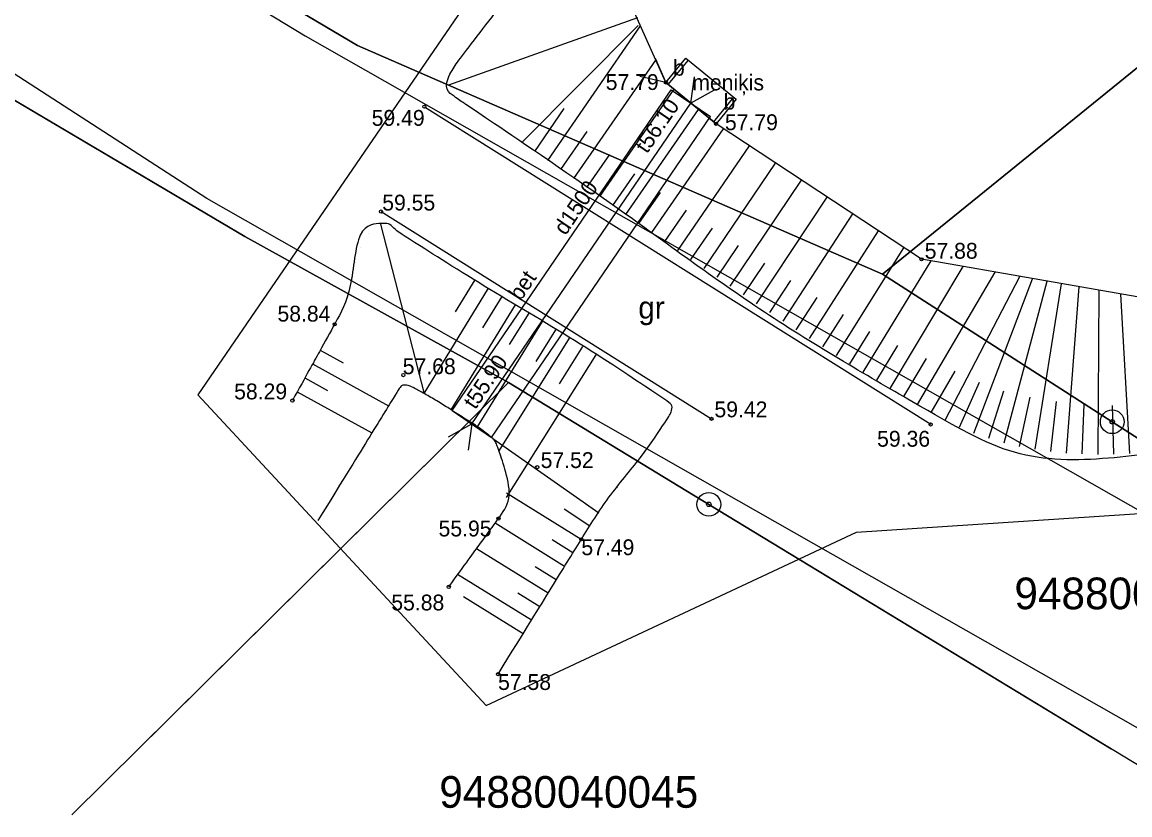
# Model space of a CAD drawing. Extents: x 616607 to 617499, y 408385 to 409695.
# Drawn here: x 616660.87 to 616695.86, y 408454.43 to 408479.45 of the extents above; entities that cross this region are included whole.
import ezdxf

# ---------------------------------------------------------------- set-up
doc = ezdxf.new("R2010")
doc.units = 0
for name, color, linetype in [('BUVE_BDET_####_####_#', 7, 'Continuous'), ('BUVE_BDET_####_TKST_#', 7, 'Continuous'), ('BUVE_INZE_VEKT_####_#', 7, 'Continuous'), ('CELI_CSEG_####_TKST_#', 7, 'Continuous'), ('CELI_TAKA_####_####_#', 7, 'Continuous'), ('HIDG_GRAV_####_####_#', 7, 'Continuous'), ('HIDG_PLIN_####_####_#', 7, 'Continuous'), ('HIDT_CAUR_####_####_#', 7, 'Continuous'), ('HIDT_CAUR_####_TKST_#', 7, 'Continuous'), ('HIDT_CAUR_KONT_####_#', 7, 'Continuous'), ('HIDT_ELEM_####_####_#', 7, 'Continuous'), ('RAMI_UZMR_####_####_#', 7, 'Continuous'), ('RELJ_AATZ_####_TKST_#', 7, 'Continuous'), ('RELJ_ELEM_####_####_#', 7, 'Continuous'), ('RELJ_NOGA_####_####_#', 7, 'Continuous'), ('ROBZ_IERR_####_####_#', 7, 'Continuous'), ('ROBZ_PROJ_####_####_#', 7, 'Continuous'), ('ROBZ_PROJ_####_TKST_#', 7, 'Continuous'), ('ROBZ_ROBP_####_####_#', 7, 'Continuous'), ('ROBZ_UZMR_####_####_#', 7, 'Continuous'), ('ROBZ_UZMR_####_TKST_#', 7, 'Continuous')]:
    doc.layers.add(name, color=color, linetype=linetype)

# ---------------------------------------------------------------- blocks, each defined once
blk = doc.blocks.new('PKT')
at = {"layer": 'RELJ_ELEM_####_####_#'}
blk.add_circle((0, 0), 0.05, dxfattribs=at)
blk = doc.blocks.new('CAURT')
at = {"layer": 'HIDT_ELEM_####_####_#'}
blk.add_lwpolyline([(0.75, -0.374), (0, 0), (0.75, 0.376)], dxfattribs=at)
blk = doc.blocks.new('KUPICA')
at = {"layer": 'ROBZ_ROBP_####_####_#'}
for radius in [0.375, 0.0702, 0.0702]:
    blk.add_circle((0, 0), radius, dxfattribs=at)

msp = doc.modelspace()

# ---------------------------------------------------------------- linework, layer by layer
at = {"layer": 'BUVE_BDET_####_####_#'}
for p, q in [((616681.206, 408477.551), (616681.842, 408478.323)), ((616681.283, 408477.488), (616681.919, 408478.26)), ((616681.842, 408478.323), (616683.426, 408477.019)), ((616683.349, 408477.082), (616682.714, 408476.31)), ((616683.426, 408477.019), (616682.791, 408476.247))]:
    msp.add_line(p, q, dxfattribs=at)
msp.add_lwpolyline([(616681.206, 408477.551), (616682.791, 408476.247)], dxfattribs=at)
at = {"layer": 'BUVE_INZE_VEKT_####_#'}
for points in [[(616654.058, 408488.574), (616669.817, 408479.019), (616700.989, 408461.293)], [(616697.261, 408456.511), (616666.703, 408473.888), (616651.742, 408483.567)]]:
    msp.add_lwpolyline(points, dxfattribs=at)
at = {"layer": 'CELI_TAKA_####_####_#'}
for points in [[(616673.578, 408476.785), (616689.576, 408466.769)], [(616672.21, 408473.475), (616682.648, 408466.933)]]:
    msp.add_lwpolyline(points, dxfattribs=at)
at = {"layer": 'HIDG_GRAV_####_####_#'}
msp.add_lwpolyline([(616765.45, 408526.57), (616717.618, 408497.675), (616716.98, 408493.818), (616722.239, 408486.737), (616723.371, 408480.51), (616720.037, 408475.133), (616696.755, 408470.663), (616689.283, 408471.969), (616682.791, 408476.247), (616681.206, 408477.551), (616679.98, 408480.284), (616680.025, 408480.874), (616680.52, 408481.458), (616702.717, 408488.625), (616709.142, 408492.712), (616711.432, 408499.757), (616715.088, 408513.471), (616726.56, 408522.413), (616768.796, 408535.775)], dxfattribs=at)
at = {"layer": 'HIDG_PLIN_####_####_#'}
msp.add_open_spline([(616674.349, 408461.628), (616674.873, 408462.347), (616675.396, 408463.066), (616675.92, 408463.785), (616676.348, 408464.373), (616676.16, 408465.278), (616675.92, 408465.965), (616675.871, 408466.105), (616675.814, 408466.252), (616675.694, 408466.348), (616675.292, 408466.672), (616674.881, 408466.922), (616674.456, 408467.195), (616674.074, 408467.44), (616673.687, 408467.668), (616673.296, 408467.884), (616673.147, 408467.966), (616672.871, 408468.03), (616672.781, 408467.884), (616671.926, 408466.495), (616671.07, 408465.107), (616670.215, 408463.719)], degree=3, dxfattribs=at)
at = {"layer": 'HIDT_CAUR_####_####_#'}
msp.add_lwpolyline([(616675.075, 408466.771), (616681.998, 408476.899)], dxfattribs=at)
at = {"layer": 'HIDT_CAUR_KONT_####_#'}
for p, q in [((616674.456, 408467.195), (616681.379, 408477.322)), ((616675.694, 408466.348), (616682.618, 408476.476))]:
    msp.add_line(p, q, dxfattribs=at)
for points in [[(616681.379, 408477.322), (616682.618, 408476.476)], [(616674.456, 408467.195), (616675.694, 408466.348)]]:
    msp.add_lwpolyline(points, dxfattribs=at)
at = {"layer": 'RAMI_UZMR_####_####_#'}
for points in [[(617191.828, 409115.62), (617145.545, 408952.8), (617072.809, 408766.141), (616965.332, 408652.076), (616939.432, 408594.661), (616924.839, 408592.467), (616706.433, 408526.081), (616666.426, 408467.691)], [(616666.426, 408467.691), (616675.529, 408457.882), (616687.228, 408463.356), (616723.888, 408465.775), (616753.554, 408507.232), (616948.282, 408568.831), (616981.528, 408608.531), (617014.563, 408672.892), (617101.571, 408748.246), (617213.472, 409074.039)]]:
    msp.add_lwpolyline(points, dxfattribs=at)
at = {"layer": 'RELJ_NOGA_####_####_#'}
for p, q in [((616674.349, 408477.472), (616680.323, 408479.605)), ((616675.366, 408479.162), (616675.366, 408479.161)), ((616676.652, 408475.657), (616680.337, 408479.352)), ((616677.476, 408475.09), (616680.406, 408479.334)), ((616675.061, 408478.766), (616675.061, 408478.766)), ((616674.757, 408478.368), (616674.758, 408478.368)), ((616678.298, 408474.521), (616680.89, 408478.256)), ((616674.488, 408477.948), (616674.488, 408477.948)), ((616674.349, 408477.472), (616674.35, 408477.472)), ((616674.586, 408477.064), (616674.586, 408477.065)), ((616679.12, 408473.951), (616681.469, 408477.335)), ((616674.999, 408476.783), (616675, 408476.783)), ((616677.064, 408475.374), (616677.994, 408476.724)), ((616679.941, 408473.38), (616682.24, 408476.7)), ((616675.413, 408476.503), (616675.413, 408476.503)), ((616675.827, 408476.222), (616675.827, 408476.223)), ((616677.887, 408474.805), (616678.716, 408476.001)), ((616680.763, 408472.811), (616683.028, 408476.09)), ((616676.24, 408475.94), (616676.24, 408475.94)), ((616676.652, 408475.657), (616676.653, 408475.658)), ((616677.064, 408475.374), (616677.064, 408475.374)), ((616681.587, 408472.244), (616683.854, 408475.546)), ((616677.476, 408475.09), (616677.476, 408475.091)), ((616678.709, 408474.236), (616679.435, 408475.282)), ((616682.413, 408471.68), (616684.672, 408475.007)), ((616677.887, 408474.805), (616677.887, 408474.806)), ((616679.53, 408473.665), (616680.228, 408474.671)), ((616678.298, 408474.521), (616678.299, 408474.521)), ((616683.241, 408471.12), (616685.491, 408474.468)), ((616678.709, 408474.236), (616678.709, 408474.236)), ((616679.12, 408473.951), (616679.12, 408473.951)), ((616680.352, 408473.096), (616681.035, 408474.081)), ((616684.073, 408470.565), (616686.304, 408473.932)), ((616679.53, 408473.665), (616679.53, 408473.666)), ((616679.941, 408473.38), (616679.942, 408473.381)), ((616681.175, 408472.528), (616681.855, 408473.515)), ((616684.908, 408470.015), (616687.111, 408473.4)), ((616672.195, 408473.083), (616673.576, 408467.726)), ((616672.641, 408472.929), (616672.64, 408472.929)), ((616680.352, 408473.096), (616680.352, 408473.096)), ((616682, 408471.962), (616682.679, 408472.956)), ((616685.748, 408469.472), (616687.921, 408472.867)), ((616671.807, 408472.783), (616671.807, 408472.783)), ((616673.049, 408472.642), (616673.048, 408472.641)), ((616680.763, 408472.811), (616680.764, 408472.812)), ((616681.175, 408472.528), (616681.175, 408472.528)), ((616671.571, 408472.343), (616671.572, 408472.343)), ((616673.472, 408472.375), (616673.472, 408472.375)), ((616681.587, 408472.244), (616681.588, 408472.245)), ((616682.827, 408471.4), (616683.504, 408472.4)), ((616686.593, 408468.937), (616688.729, 408472.334)), ((616671.403, 408471.873), (616671.404, 408471.873)), ((616673.896, 408472.11), (616673.895, 408472.109)), ((616674.32, 408471.845), (616674.32, 408471.845)), ((616682, 408471.962), (616682, 408471.962)), ((616683.657, 408470.842), (616684.33, 408471.848)), ((616687.442, 408468.409), (616689.591, 408471.916)), ((616674.745, 408471.582), (616674.745, 408471.582)), ((616682.413, 408471.68), (616682.413, 408471.681)), ((616688.297, 408467.891), (616690.598, 408471.739)), ((616689.158, 408467.381), (616691.606, 408471.563)), ((616671.261, 408471.393), (616671.262, 408471.393)), ((616675.171, 408471.32), (616674.55, 408470.311)), ((616682.827, 408471.4), (616682.827, 408471.4)), ((616683.241, 408471.12), (616683.242, 408471.121)), ((616684.49, 408470.289), (616685.157, 408471.301)), ((616690.028, 408466.889), (616692.384, 408471.427)), ((616690.941, 408466.482), (616692.785, 408471.357)), ((616691.893, 408466.178), (616693.25, 408471.276)), ((616692.871, 408465.971), (616693.702, 408471.197)), ((616693.864, 408465.853), (616694.261, 408471.099)), ((616671.123, 408470.913), (616671.123, 408470.913)), ((616675.597, 408471.058), (616673.557, 408467.737)), ((616676.023, 408470.796), (616675.413, 408469.803)), ((616683.657, 408470.842), (616683.657, 408470.842)), ((616685.328, 408469.743), (616685.986, 408470.759)), ((616694.863, 408465.812), (616694.896, 408470.988)), ((616695.862, 408465.838), (616695.579, 408470.869)), ((616670.969, 408470.437), (616670.97, 408470.437)), ((616676.449, 408470.534), (616674.414, 408467.221)), ((616684.073, 408470.565), (616684.073, 408470.566)), ((616676.875, 408470.273), (616676.262, 408469.277)), ((616684.49, 408470.289), (616684.49, 408470.289)), ((616686.17, 408469.204), (616686.816, 408470.223)), ((616670.773, 408469.977), (616670.774, 408469.977)), ((616677.3, 408470.01), (616675.245, 408466.681)), ((616677.726, 408469.747), (616677.101, 408468.74)), ((616684.908, 408470.015), (616684.909, 408470.016)), ((616685.328, 408469.743), (616685.328, 408469.743)), ((616670.532, 408469.539), (616670.533, 408469.539)), ((616678.15, 408469.483), (616675.934, 408465.923)), ((616685.748, 408469.472), (616685.749, 408469.473)), ((616687.017, 408468.672), (616687.649, 408469.693)), ((616670.29, 408469.102), (616671.015, 408468.701)), ((616678.574, 408469.219), (616677.835, 408468.037)), ((616686.17, 408469.204), (616686.17, 408469.204)), ((616687.869, 408468.149), (616688.537, 408469.252)), ((616670.048, 408468.664), (616672.445, 408467.339)), ((616678.998, 408468.952), (616676.162, 408464.448)), ((616679.42, 408468.684), (616679.42, 408468.684)), ((616686.593, 408468.937), (616686.593, 408468.938)), ((616687.017, 408468.672), (616687.017, 408468.672)), ((616688.727, 408467.635), (616689.438, 408468.84)), ((616679.841, 408468.415), (616679.84, 408468.414)), ((616687.442, 408468.409), (616687.443, 408468.41)), ((616689.59, 408467.131), (616690.342, 408468.435)), ((616669.806, 408468.227), (616670.519, 408467.832)), ((616680.261, 408468.143), (616680.261, 408468.143)), ((616687.869, 408468.149), (616687.869, 408468.149)), ((616690.479, 408466.673), (616691.113, 408468.088)), ((616669.564, 408467.789), (616671.92, 408466.486)), ((616680.679, 408467.869), (616680.679, 408467.869)), ((616688.297, 408467.891), (616688.298, 408467.892)), ((616688.727, 408467.635), (616688.727, 408467.635)), ((616691.413, 408466.318), (616691.886, 408467.819)), ((616692.38, 408466.063), (616692.714, 408467.614)), ((616681.096, 408467.593), (616681.096, 408467.593)), ((616689.158, 408467.381), (616689.158, 408467.382)), ((616693.366, 408465.902), (616693.552, 408467.475)), ((616694.363, 408465.823), (616694.426, 408467.39)), ((616695.363, 408465.817), (616695.32, 408467.352)), ((616681.376, 408467.227), (616681.375, 408467.227)), ((616689.59, 408467.131), (616689.59, 408467.131)), ((616681.152, 408466.786), (616681.152, 408466.786)), ((616690.028, 408466.889), (616690.028, 408466.89)), ((616690.479, 408466.673), (616690.479, 408466.673)), ((616679.088, 408463.96), (616675.746, 408466.3)), ((616680.867, 408466.376), (616680.866, 408466.377)), ((616690.941, 408466.482), (616690.941, 408466.483)), ((616691.413, 408466.318), (616691.413, 408466.318)), ((616680.573, 408465.971), (616680.573, 408465.971)), ((616691.893, 408466.178), (616691.893, 408466.179)), ((616692.38, 408466.063), (616692.38, 408466.063)), ((616692.871, 408465.971), (616692.871, 408465.972)), ((616693.366, 408465.902), (616693.366, 408465.902)), ((616693.864, 408465.853), (616693.864, 408465.854)), ((616680.275, 408465.57), (616680.274, 408465.571)), ((616694.363, 408465.823), (616694.363, 408465.823)), ((616694.863, 408465.812), (616694.863, 408465.813)), ((616695.363, 408465.817), (616695.363, 408465.818)), ((616695.862, 408465.838), (616695.862, 408465.839)), ((616679.974, 408465.17), (616679.974, 408465.17)), ((616678.536, 408463.126), (616676.173, 408464.588)), ((616679.675, 408464.77), (616679.674, 408464.771)), ((616679.378, 408464.367), (616679.378, 408464.368)), ((616678.806, 408463.547), (616677.994, 408464.086)), ((616678.01, 408462.276), (616675.811, 408463.636)), ((616678.273, 408462.701), (616677.613, 408463.11)), ((616677.484, 408461.425), (616675.221, 408462.825)), ((616676.959, 408460.575), (616674.63, 408462.015)), ((616677.747, 408461.851), (616677.078, 408462.265)), ((616676.696, 408460.15), (616674.81, 408461.315)), ((616677.222, 408461), (616676.533, 408461.426)), ((616676.433, 408459.724), (616676.432, 408459.725)), ((616676.17, 408459.299), (616676.169, 408459.299)), ((616675.907, 408458.874), (616675.906, 408458.874))]:
    msp.add_line(p, q, dxfattribs=at)
for points in [[(616975.731, 408606.41), (616971.71, 408604.144), (616967.689, 408601.878), (616963.668, 408599.612), (616962.341, 408598.864), (616961.192, 408597.791), (616960.311, 408596.511), (616959.39, 408595.173), (616958.675, 408593.776), (616958.002, 408592.329), (616957.302, 408590.825), (616956.736, 408589.272), (616956.015, 408587.778), (616955.313, 408586.324), (616954.582, 408584.882), (616953.626, 408583.572), (616952.496, 408582.025), (616951.261, 408580.593), (616950.022, 408579.143), (616948.785, 408577.695), (616947.537, 408576.278), (616946.22, 408574.895), (616945.626, 408574.271), (616944.957, 408573.742), (616944.225, 408573.278), (616943.451, 408572.788), (616942.648, 408572.387), (616941.804, 408572.051), (616941, 408571.73), (616940.2, 408571.414), (616939.368, 408571.187), (616938.69, 408571.002), (616938.005, 408570.852), (616937.329, 408570.663), (616918.615, 408565.441), (616899.903, 408560.204), (616881.253, 408554.75), (616874.57, 408552.796), (616867.991, 408550.484), (616861.269, 408548.669), (616855.483, 408547.106), (616849.688, 408545.577), (616843.9, 408544.023), (616838.111, 408542.469), (616832.323, 408540.916), (616826.537, 408539.352), (616816.497, 408536.637), (616806.51, 408533.737), (616796.541, 408530.774), (616791.553, 408529.292), (616786.584, 408527.751), (616781.609, 408526.226), (616776.622, 408524.697), (616771.656, 408523.11), (616766.688, 408521.515), (616762.607, 408520.204), (616758.677, 408518.521), (616754.775, 408516.687), (616750.921, 408514.875), (616747.341, 408512.653), (616743.915, 408510.109), (616740.341, 408507.454), (616736.942, 408504.677), (616733.801, 408501.555), (616732.131, 408499.895), (616730.49, 408498.223), (616728.926, 408496.468), (616728.114, 408495.556), (616727.318, 408494.632), (616726.518, 408493.709), (616725.695, 408492.76), (616724.91, 408491.864), (616724.122, 408490.803), (616723.665, 408490.187), (616723.18, 408489.459), (616723.332, 408488.764), (616723.537, 408487.829), (616723.949, 408486.896), (616724.213, 408485.954), (616724.975, 408483.236), (616725.742, 408480.486), (616726.381, 408477.738), (616726.631, 408476.667), (616726.554, 408475.507), (616726.221, 408474.429), (616726.043, 408473.855), (616725.77, 408473.346), (616725.415, 408472.86), (616725.226, 408472.602), (616725.032, 408472.37), (616724.813, 408472.14), (616724.582, 408471.898), (616724.347, 408471.683), (616724.071, 408471.48), (616723.783, 408471.268), (616723.475, 408471.091), (616723.13, 408471.039), (616722.812, 408470.991), (616722.494, 408470.986), (616722.176, 408470.982), (616721.543, 408470.975), (616720.901, 408471.154), (616720.278, 408471.02), (616716.569, 408470.219), (616712.93, 408469.339), (616709.261, 408468.478), (616707.424, 408468.047), (616705.589, 408467.613), (616703.751, 408467.182), (616701.927, 408466.754), (616700.076, 408466.424), (616698.236, 408466.115), (616695.42, 408465.64), (616692.315, 408465.565), (616689.691, 408467.073), (616684.319, 408470.158), (616679.892, 408473.486), (616675.008, 408476.777), (616674.831, 408476.896), (616674.652, 408477.012), (616674.483, 408477.14), (616674.175, 408477.376), (616674.46, 408477.978), (616674.696, 408478.288), (616675.427, 408479.251), (616676.165, 408480.2), (616676.939, 408481.135), (616677.893, 408482.289), (616678.812, 408483.429), (616679.848, 408484.532), (616681.078, 408485.839), (616682.698, 408486.726), (616684.412, 408487.237), (616686.183, 408487.764), (616687.958, 408488.143), (616689.768, 408488.401), (616691.642, 408488.668), (616693.528, 408488.826), (616695.398, 408489.116), (616696.323, 408489.26), (616697.239, 408489.444), (616698.155, 408489.647), (616699.054, 408489.848), (616699.912, 408490.166), (616700.785, 408490.476), (616703.122, 408491.305), (616705.613, 408491.942), (616707.248, 408494.043), (616707.429, 408494.275), (616707.474, 408494.537), (616707.552, 408494.798), (616707.628, 408495.051), (616707.711, 408495.3), (616707.761, 408495.559), (616707.86, 408496.068), (616707.943, 408496.577), (616707.977, 408497.092), (616708.044, 408498.12), (616708.108, 408499.147), (616708.168, 408500.175), (616708.254, 408501.63), (616708.34, 408503.085), (616708.414, 408504.54), (616708.488, 408505.998), (616708.403, 408507.461), (616708.436, 408508.92), (616708.468, 408510.38), (616708.539, 408511.837), (616708.686, 408513.293), (616708.76, 408514.026), (616708.887, 408514.749), (616709.039, 408515.47), (616709.116, 408515.834), (616709.208, 408516.193), (616709.297, 408516.554), (616709.387, 408516.92), (616709.487, 408517.278), (616709.619, 408517.635), (616710.681, 408520.51), (616712.959, 408522.898), (616715.736, 408524.335), (616718.688, 408525.863), (616721.668, 408526.887), (616724.792, 408527.643), (616730.078, 408528.922), (616735.359, 408530.207), (616740.655, 408531.436), (616749.901, 408533.581), (616759.244, 408535.317), (616768.413, 408537.779), (616798.7, 408545.91), (616828.618, 408555.288), (616858.746, 408563.964), (616877.646, 408569.406), (616896.581, 408574.731), (616915.501, 408580.089), (616916.131, 408580.267), (616916.803, 408580.127), (616917.44, 408580.402), (616917.832, 408580.571), (616918.181, 408580.992), (616918.136, 408581.394), (616918.071, 408581.969), (616918.005, 408582.544), (616917.94, 408583.119), (616917.87, 408583.733), (616917.799, 408584.347), (616917.73, 408584.96), (616917.674, 408585.454), (616917.97, 408585.948), (616918.384, 408586.3), (616918.906, 408586.742), (616919.445, 408586.959), (616920.02, 408587.218), (616920.568, 408587.465), (616921.093, 408587.698), (616921.676, 408587.899), (616922.792, 408588.284), (616923.918, 408588.529), (616925.044, 408588.565), (616925.938, 408588.594), (616926.854, 408588.454), (616927.734, 408588.123), (616928.677, 408587.768), (616929.526, 408587.359), (616930.432, 408586.999), (616931.324, 408586.645), (616932.223, 408586.313), (616933.127, 408585.998), (616933.97, 408585.704), (616934.935, 408585.706), (616935.807, 408585.922), (616937.564, 408586.355), (616939.443, 408587.201), (616940.422, 408588.724), (616944.438, 408594.972), (616948.27, 408601.228), (616952.11, 408607.531)], [(616675.907, 408458.874), (616676.784, 408460.292), (616677.661, 408461.711), (616678.538, 408463.129), (616679.373, 408464.479), (616680.435, 408465.692), (616681.3, 408467.006), (616681.382, 408467.13), (616681.425, 408467.373), (616681.3, 408467.457), (616678.514, 408469.328), (616675.636, 408470.996), (616672.831, 408472.78), (616672.664, 408472.886), (616672.486, 408473.105), (616672.334, 408473.102), (616671.419, 408473.089), (616671.316, 408470.956), (616670.742, 408469.918), (616670.298, 408469.115), (616669.854, 408468.313), (616669.41, 408467.51)]]:
    msp.add_open_spline(points, degree=3, dxfattribs=at)
at = {"layer": 'ROBZ_IERR_####_####_#'}
for points in [[(616717.135, 408556.579), (616730.494, 408522.344), (616708.653, 408488.203), (616688.046, 408471.498), (616671.463, 408478.715), (616654.855, 408488.541)], [(616650.773, 408482.822), (616667.902, 408472.688), (616676.233, 408468.078), (616664.396, 408456.366)]]:
    msp.add_lwpolyline(points, dxfattribs=at)
at = {"layer": 'ROBZ_PROJ_####_####_#'}
for points in [[(616654.443, 408488.785), (616671.463, 408478.715), (616688.046, 408471.498), (616695.309, 408466.84), (616704.658, 408460.844)], [(616696.246, 408455.923), (616682.564, 408464.233), (616676.233, 408468.078), (616667.902, 408472.688), (616650.915, 408482.738)]]:
    msp.add_lwpolyline(points, dxfattribs=at)
at = {"layer": 'ROBZ_UZMR_####_####_#'}
for points in [[(616704.998, 408460.626), (616695.309, 408466.84), (616688.046, 408471.498), (616708.653, 408488.203), (616730.494, 408522.344), (616805.459, 408543.657), (616889.795, 408568.012), (616940.576, 408582.801), (616958.517, 408604.593), (616968.565, 408608.405), (616974.837, 408605.827), (616993.227, 408598.268)], [(616662.442, 408454.433), (616676.233, 408468.078), (616682.564, 408464.233), (616695.273, 408456.514)]]:
    msp.add_lwpolyline(points, dxfattribs=at)

# ---------------------------------------------------------------- block references
at = {"layer": 'HIDT_ELEM_####_####_#'}
for p, rotation in [((616681.206, 408477.551), 140.5378223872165), ((616681.998, 408476.899), 55.64370333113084), ((616675.075, 408466.771), -124.3562966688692)]:
    msp.add_blockref('CAURT', p, dxfattribs=dict(at, rotation=rotation))
at = {"layer": 'RELJ_ELEM_####_####_#'}
for p in [(616681.206, 408477.551), (616673.578, 408476.785), (616682.791, 408476.247), (616672.21, 408473.475), (616689.283, 408471.969), (616670.742, 408469.918), (616672.914, 408468.313), (616669.41, 408467.51), (616682.648, 408466.933), (616689.572, 408466.756), (616677.144, 408465.408), (616675.92, 408463.785), (616678.538, 408463.129), (616674.349, 408461.628), (616675.907, 408458.874)]:
    msp.add_blockref('PKT', p, dxfattribs=at)
at = {"layer": 'ROBZ_ROBP_####_####_#'}
for p in [(616695.309, 408466.84), (616682.564, 408464.233)]:
    msp.add_blockref('KUPICA', p, dxfattribs=at)

# ---------------------------------------------------------------- texts
at = {"layer": 'BUVE_BDET_####_TKST_#'}
for s, p in [('b', (616681.432, 408477.765)), ('meniķis', (616682.042, 408477.301)), ('b', (616683.031, 408476.696))]:
    msp.add_text(s, height=0.5, dxfattribs=at).set_placement(p)
at = {"layer": 'CELI_CSEG_####_TKST_#'}
msp.add_text('gr', height=0.7, dxfattribs=at).set_placement((616680.337, 408470.095))
at = {"layer": 'HIDT_CAUR_####_TKST_#'}
for s, p in [('t56.10', (616680.611, 408475.28)), ('d1500', (616678.037, 408472.698)), ('bet', (616676.618, 408470.623)), ('t55.90', (616675.187, 408467.201))]:
    msp.add_text(s, height=0.5, rotation=55.6437, dxfattribs=at).set_placement(p)
at = {"layer": 'RELJ_AATZ_####_TKST_#'}
for s, p in [('57.79', (616679.307, 408477.314)), ('59.49', (616671.914, 408476.183)), ('57.79', (616683.073, 408476.045)), ('59.55', (616672.248, 408473.508)), ('57.88', (616689.384, 408471.987)), ('58.84', (616668.938, 408470.003)), ('57.68', (616672.895, 408468.342)), ('58.29', (616667.569, 408467.548)), ('59.42', (616682.742, 408466.981)), ('59.36', (616687.88, 408466.053)), ('57.52', (616677.252, 408465.38)), ('55.95', (616674.027, 408463.22)), ('57.49', (616678.538, 408462.629)), ('55.88', (616672.534, 408460.885)), ('57.58', (616675.907, 408458.374))]:
    msp.add_text(s, height=0.5, dxfattribs=at).set_placement(p)
at = {"layer": 'ROBZ_PROJ_####_TKST_#'}
msp.add_text('94880040065', height=1, dxfattribs=at).set_placement((616692.217, 408460.922))
at = {"layer": 'ROBZ_UZMR_####_TKST_#'}
msp.add_text('94880040045', height=1, dxfattribs=at).set_placement((616674.049, 408454.656))

doc.saveas('drawing.dxf')
